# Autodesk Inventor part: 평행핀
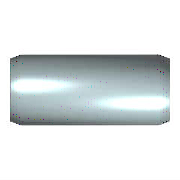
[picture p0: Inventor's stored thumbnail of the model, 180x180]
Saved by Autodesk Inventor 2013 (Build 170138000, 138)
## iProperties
IsCustomPart: 0
Created: 2009-02
Part Number: 평행핀
Material: 강, 연강
Description: 평행 핀
Document SubType Name: Modeling
Standard: KS B 1320
Designer: KYOUNG IL JANG
Standards Organization: KS
Language: ko-KR
Size Designation: B 5 x  20
Categories: <MemberInstance><Categories><Category DisplayName="조임쇠" InternalName="e4da775c-781d-43d5-af7c-5136215cf5a6" Mnemonic="FSTN"><Category DisplayName="핀" InternalNa
Density: 1 g/cm^3
Author: KYOUNG IL JANG
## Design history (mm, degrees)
sketch "스케치"
  geometry: C1 r 2.5 at (0, 0); 1 further point
  constraints: 1 centre point, 1 coincident
  dimensions: "d1" = 5 diameter of C1 (= NND)
extrude "본체" new body sketch "스케치" distance "d2" = 20 (= NLG); taper "d3" = 0 deg
chamfer "스케치2" distance "d8" = 0.8 (= PHH); stored, may be unused: angle "d9" = 15 deg (= FAWI), second distance "d12" = 0.8 (= PHH)
node "작업 평면1"
body "Solid1"
chamfer "모따기1" distance "d4" = 0.8 (= PHH); stored, may be unused: angle "d5" = 15 deg (= FAWI), second distance "d11" = 0.8 (= PHH)
other parameters: "NND" = 5 [user parameter; used in 1 equation term], "NLG" = 20 [user parameter; used in 1 equation term], "PHH" = 0.8 [user parameter; used in 4 equation terms], "FAWI" = 15 deg [user parameter; used in 2 equation terms], "d13" = 0, "d15" = 0, "d16" = 0, "KAH" = 0.63 [user parameter]
